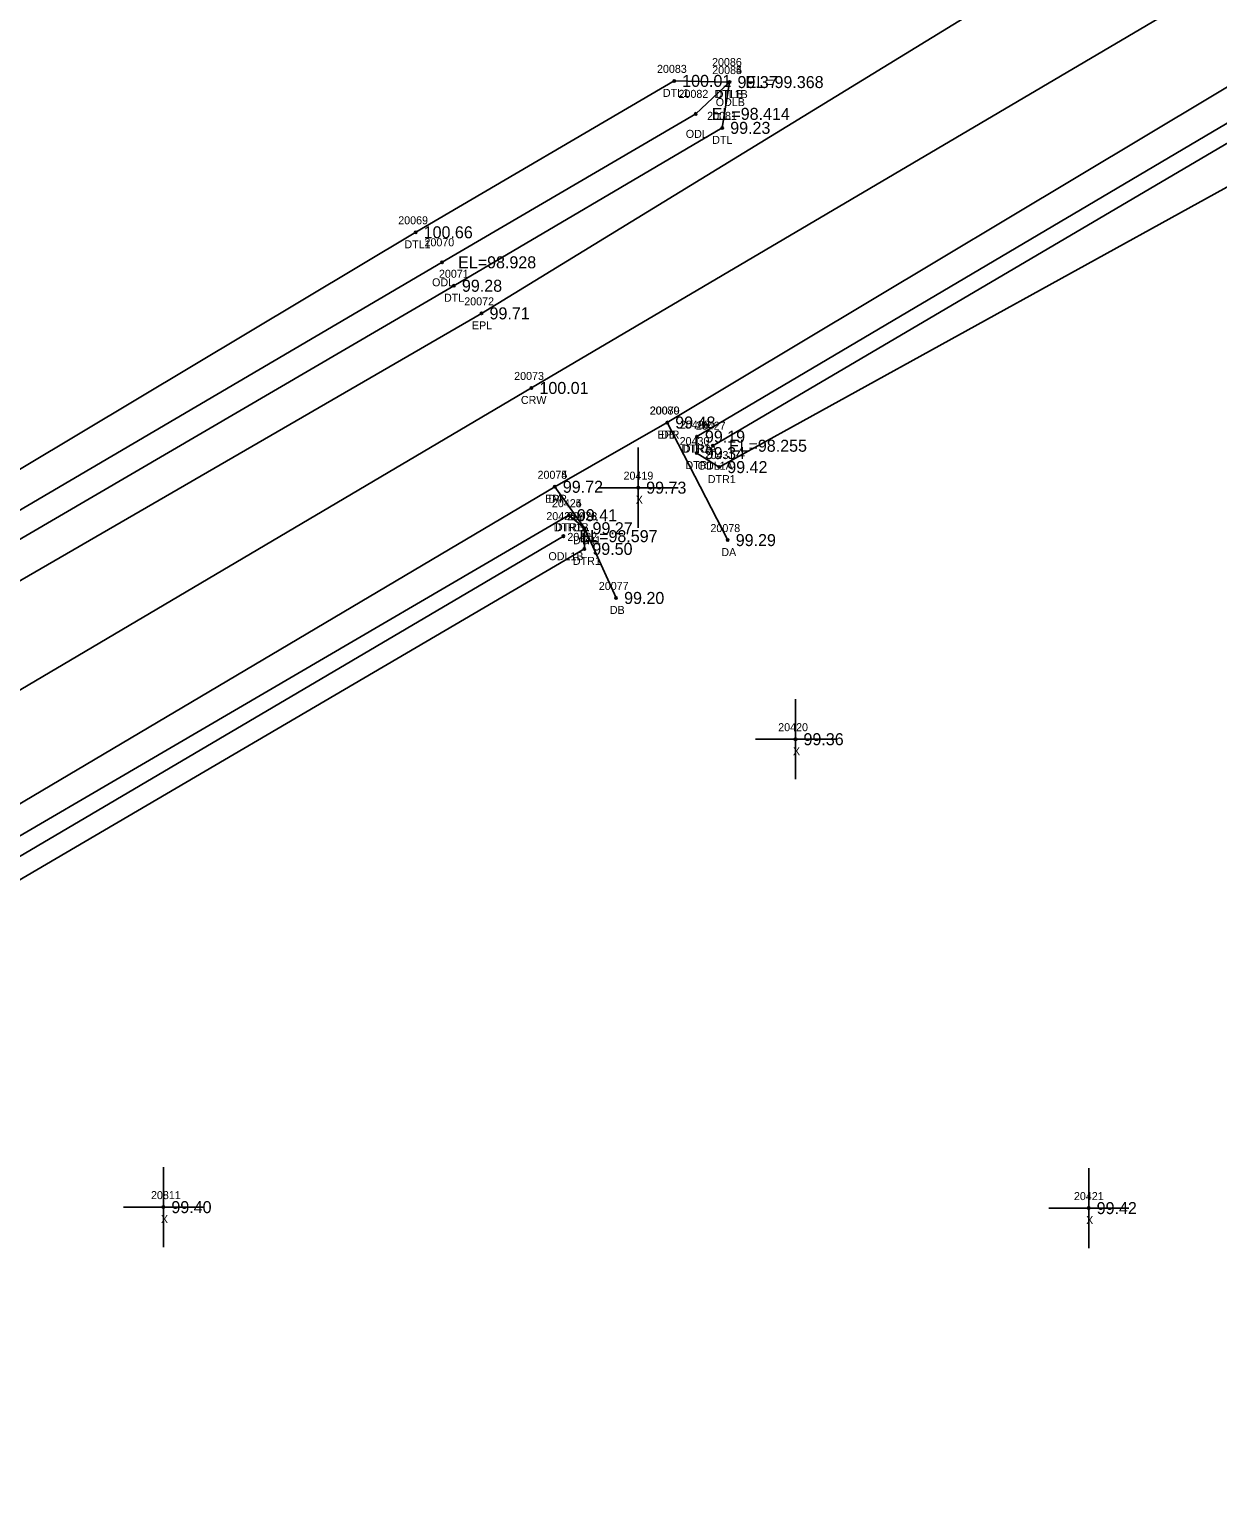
# Model space of a CAD drawing. Extents: x 2530197 to 2532051, y 935230 to 936631.
# Drawn here: x 2530638.9 to 2530787.5, y 935572.8 to 935755.5 of the extents above; entities that cross this region are included whole.
import ezdxf

# ---------------------------------------------------------------- set-up
doc = ezdxf.new("R2010")
doc.units = 0
for name, color, linetype in [('RD_DTM_BkLn1', 7, 'Continuous'), ('RD_EX_Driveway', 7, 'Continuous'), ('RD_EX_Driveway_txCode', 7, 'Continuous'), ('RD_EX_H2O', 7, 'Continuous'), ('RD_EX_H2O_txCode', 7, 'Continuous'), ('RD_EX_Misc', 7, 'Continuous'), ('RD_EX_Misc_txCode', 7, 'Continuous'), ('RD_EX_Road', 7, 'Continuous'), ('RD_EX_Road_txCode', 7, 'Continuous'), ('RD_EX_TX_Driveway_ELEV', 7, 'Continuous'), ('RD_EX_TX_H2O_ELEV', 7, 'Continuous'), ('RD_EX_TX_Misc_ELEV', 7, 'Continuous'), ('RD_EX_TX_Road_ELEV', 7, 'Continuous'), ('RD_HC_Survey_ELEV', 7, 'Continuous'), ('RD_HC_Survey_txCode', 7, 'Continuous'), ('RD_SMD_Locator', 7, 'Continuous')]:
    doc.layers.add(name, color=color, linetype=linetype)

msp = doc.modelspace()

# ---------------------------------------------------------------- linework, layer by layer
at = {"layer": 'RD_DTM_BkLn1'}
msp.add_lwpolyline([(2530212.5, 935590.24), (2530312.97, 935590.25), (2530414.21, 935590.57), (2530470.01, 935593.88), (2530526.51, 935611.77), (2530574.01, 935635.84), (2530615.35, 935659.73), (2530701.7, 935710.7), (2530789.3, 935762.35), (2530874.46, 935813.14), (2530961.78, 935865.4), (2531046.63, 935916.04), (2531084.76, 935938.51)], dxfattribs=at)
at = {"layer": 'RD_EX_Driveway'}
msp.add_line((2530726.23, 935691.69), (2530718.67, 935706.38), dxfattribs=at)
msp.add_lwpolyline([(2530704.62, 935698.35), (2530708.33, 935693.17), (2530712.28, 935684.46)], dxfattribs=at)
at = {"layer": 'RD_EX_H2O'}
for points in [[(2530722.38, 935704.62), (2530796.68, 935748.53), (2530872.47, 935794.26), (2530874.44, 935791.96), (2530875.06, 935785.48)], [(2530724.37, 935703.48), (2530797.51, 935746.5), (2530871.29, 935790.63)], [(2530722.38, 935704.62), (2530722.37, 935702.56), (2530725.17, 935700.81), (2530799.94, 935742.04), (2530875.06, 935785.48)], [(2530543.2, 935642.77), (2530561.27, 935656.09), (2530603.32, 935679.95), (2530687.23, 935730.15), (2530719.54, 935749.07), (2530726.45, 935748.92)], [(2530543.2, 935642.77), (2530564.55, 935651.29), (2530607.02, 935673.87), (2530692.01, 935723.47), (2530725.54, 935743.2), (2530726.45, 935748.92)], [(2530543.2, 935642.77), (2530563.37, 935652.64), (2530605.31, 935676.39), (2530690.53, 935726.4), (2530722.23, 935744.95), (2530726.45, 935748.92)], [(2530585.61, 935271.89), (2530554.63, 935366.84), (2530523, 935462.44), (2530497.71, 935534.53), (2530497.63, 935550.35), (2530501.9, 935567.07), (2530512.76, 935580.06), (2530532.29, 935593.54), (2530580.75, 935621.41), (2530622.78, 935645.99), (2530706.38, 935694.8)], [(2530592.81, 935273.73), (2530561.2, 935369.39), (2530529.39, 935464.13), (2530504.24, 935535.46), (2530502.94, 935549.83), (2530506.75, 935563.82), (2530516.63, 935575.2), (2530535.16, 935588.8), (2530583.24, 935617.5), (2530624.86, 935641.7), (2530708.31, 935690.59), (2530708.33, 935693.17), (2530706.38, 935694.8)], [(2530587.86, 935272.38), (2530557.35, 935368.29), (2530525.38, 935463.03), (2530500.38, 935535.14), (2530499.61, 935550.4), (2530504.44, 935565.67), (2530514.36, 935577.87), (2530533.45, 935591.79), (2530582.01, 935619.78), (2530623.26, 935643.67), (2530705.7, 935692.18)]]:
    msp.add_lwpolyline(points, dxfattribs=at)
at = {"layer": 'RD_EX_Misc'}
for p, q in [((2530715.04, 935693.24), (2530715.04, 935703.24)), ((2530710.04, 935698.24), (2530720.04, 935698.24)), ((2530734.7, 935661.81), (2530734.7, 935671.81)), ((2530729.7, 935666.81), (2530739.7, 935666.81)), ((2530655.7, 935603.34), (2530655.7, 935613.34)), ((2530771.34, 935603.22), (2530771.34, 935613.22)), ((2530650.7, 935608.34), (2530660.7, 935608.34)), ((2530766.34, 935608.22), (2530776.34, 935608.22))]:
    msp.add_line(p, q, dxfattribs=at)
at = {"layer": 'RD_EX_Road'}
for points in [[(2530213.13, 935600.16), (2530313.8, 935600.81), (2530414.15, 935601.13), (2530426.72, 935601.43), (2530429.46, 935603.55), (2530467.67, 935608.62), (2530486.46, 935612.38), (2530518.02, 935622.55), (2530522.16, 935623.68), (2530567.91, 935646.01), (2530609.3, 935670.15), (2530695.46, 935720.02), (2530775.85, 935769.27), (2530868.29, 935824.03), (2530924.84, 935856.95), (2530956.21, 935875.82), (2531040.72, 935926.38), (2531079.45, 935947.76)], [(2530212.44, 935579.72), (2530312.61, 935580.14), (2530402.98, 935580.64), (2530451.06, 935579.53), (2530466.91, 935580.35), (2530487.45, 935583.29), (2530533.43, 935598.45), (2530580.28, 935625.08), (2530621.69, 935649.23), (2530704.62, 935698.35), (2530718.67, 935706.38), (2530795.45, 935752.36), (2530871.33, 935796.67), (2530882.4, 935803.04), (2530947.17, 935842.26), (2530966, 935852.42), (2530992.72, 935868), (2531009.49, 935879.01), (2531052.39, 935904.85), (2531090.88, 935928.23)]]:
    msp.add_lwpolyline(points, dxfattribs=at)
at = {"layer": 'RD_SMD_Locator'}
for centre in [(2530719.54, 935749.07), (2530726.45, 935748.92), (2530726.45, 935748.92), (2530726.45, 935748.92), (2530722.23, 935744.95), (2530725.54, 935743.2), (2530687.23, 935730.15), (2530690.53, 935726.4), (2530692.01, 935723.47), (2530695.46, 935720.02), (2530701.7, 935710.7), (2530718.67, 935706.38), (2530718.67, 935706.38), (2530722.38, 935704.62), (2530722.38, 935704.62), (2530722.37, 935702.56), (2530724.37, 935703.48), (2530725.17, 935700.81), (2530704.62, 935698.35), (2530704.62, 935698.35), (2530715.04, 935698.24), (2530706.38, 935694.8), (2530706.38, 935694.8), (2530708.33, 935693.17), (2530708.33, 935693.17), (2530705.7, 935692.18), (2530726.23, 935691.69), (2530708.31, 935690.59), (2530712.28, 935684.46), (2530734.7, 935666.81), (2530655.7, 935608.34), (2530771.34, 935608.22)]:
    msp.add_circle(centre, 0.15, dxfattribs=at)

# ---------------------------------------------------------------- texts
at = {"layer": 'RD_EX_Driveway_txCode'}
for s, p in [('20079', (2530716.51, 935707.38)), ('DB', (2530717.89, 935704.38)), ('20075', (2530702.46, 935699.35)), ('DA', (2530703.82, 935696.35)), ('20076', (2530706.14, 935694.17)), ('20078', (2530724.07, 935692.69)), ('D', (2530708.02, 935691.17)), ('DA', (2530725.43, 935689.69)), ('20077', (2530710.12, 935685.46)), ('DB', (2530711.5, 935682.46))]:
    msp.add_text(s, height=1, dxfattribs=at).set_placement(p)
at = {"layer": 'RD_EX_H2O_txCode'}
for s, p in [('20086', (2530724.27, 935750.92)), ('20083', (2530717.39, 935750.07)), ('20084', (2530724.29, 935749.92)), ('20085', (2530724.29, 935749.92)), ('DTL1', (2530718.13, 935747.07)), ('20082', (2530720.08, 935746.95)), ('DTL1B', (2530724.57, 935746.92)), ('ODLB', (2530724.73, 935745.92)), ('DTLB', (2530724.73, 935746.92)), ('20081', (2530723.66, 935744.2)), ('ODL', (2530720.99, 935741.95)), ('DTL', (2530724.29, 935741.2)), ('20069', (2530685.05, 935731.15)), ('DTL1', (2530685.82, 935728.15)), ('20070', (2530688.33, 935728.4)), ('ODL', (2530689.28, 935723.4)), ('20071', (2530690.14, 935724.47)), ('DTL', (2530690.77, 935721.47)), ('20428', (2530720.26, 935705.62)), ('20429', (2530720.26, 935705.62)), ('20427', (2530722.25, 935705.48)), ('20430', (2530720.22, 935703.56)), ('DTR1A', (2530720.46, 935702.62)), ('DTRA', (2530720.62, 935702.62)), ('20431', (2530723.34, 935701.81)), ('DTR1', (2530720.94, 935700.56)), ('ODL1A', (2530722.47, 935700.48)), ('DTR1', (2530723.74, 935698.81)), ('20424', (2530704.26, 935695.8)), ('20425', (2530704.26, 935695.8)), ('20426', (2530703.56, 935694.18)), ('20423', (2530706.21, 935694.17)), ('DTR1B', (2530704.47, 935692.8)), ('DTRB', (2530704.64, 935692.8)), ('20422', (2530706.19, 935691.59)), ('DTR1', (2530706.89, 935691.17)), ('ODL1B', (2530703.82, 935689.18)), ('DTR1', (2530706.88, 935688.59))]:
    msp.add_text(s, height=1, dxfattribs=at).set_placement(p)
at = {"layer": 'RD_EX_Misc_txCode'}
for s, p in [('20419', (2530713.21, 935699.24)), ('X', (2530714.73, 935696.24)), ('20420', (2530732.54, 935667.81)), ('X', (2530734.38, 935664.81)), ('20811', (2530654.15, 935609.34)), ('20421', (2530769.5, 935609.22)), ('X', (2530655.39, 935606.34)), ('X', (2530771.02, 935606.22))]:
    msp.add_text(s, height=1, dxfattribs=at).set_placement(p)
at = {"layer": 'RD_EX_Road_txCode'}
for s, p in [('20072', (2530693.3, 935721.02)), ('EPL', (2530694.26, 935718.02)), ('20080', (2530716.47, 935707.38)), ('EPR', (2530717.44, 935704.38)), ('20074', (2530702.46, 935699.35)), ('EPR', (2530703.39, 935696.35))]:
    msp.add_text(s, height=1, dxfattribs=at).set_placement(p)
at = {"layer": 'RD_EX_TX_Driveway_ELEV'}
for s, p in [('99.48', (2530719.67, 935705.63)), ('99.72', (2530705.62, 935697.6)), ('99.27', (2530709.33, 935692.42)), ('99.29', (2530727.23, 935690.94)), ('99.20', (2530713.28, 935683.71))]:
    msp.add_text(s, height=1.5, dxfattribs=at).set_placement(p)
at = {"layer": 'RD_EX_TX_H2O_ELEV'}
for s, p in [('100.01', (2530720.54, 935748.32)), ('99.37', (2530727.45, 935748.17)), ('99.37', (2530727.45, 935748.17)), ('EL=99.368', (2530728.45, 935748.17)), ('EL=98.414', (2530724.23, 935744.2)), ('99.23', (2530726.54, 935742.45)), ('100.66', (2530688.23, 935729.4)), ('EL=98.928', (2530692.53, 935725.65)), ('99.28', (2530693.01, 935722.72)), ('99.19', (2530723.38, 935703.87)), ('99.19', (2530723.38, 935703.87)), ('EL=98.255', (2530726.37, 935702.73)), ('99.34', (2530723.37, 935701.81)), ('99.42', (2530726.17, 935700.06)), ('99.41', (2530707.38, 935694.05)), ('99.41', (2530707.38, 935694.05)), ('99.27', (2530709.33, 935692.42)), ('EL=98.597', (2530707.7, 935691.43)), ('99.50', (2530709.31, 935689.84))]:
    msp.add_text(s, height=1.5, dxfattribs=at).set_placement(p)
at = {"layer": 'RD_EX_TX_Misc_ELEV'}
for s, p in [('99.73', (2530716.04, 935697.49)), ('99.36', (2530735.7, 935666.06)), ('99.40', (2530656.7, 935607.59)), ('99.42', (2530772.34, 935607.47))]:
    msp.add_text(s, height=1.5, dxfattribs=at).set_placement(p)
at = {"layer": 'RD_EX_TX_Road_ELEV'}
for s, p in [('99.71', (2530696.46, 935719.27)), ('99.48', (2530719.67, 935705.63)), ('99.72', (2530705.62, 935697.6))]:
    msp.add_text(s, height=1.5, dxfattribs=at).set_placement(p)
at = {"layer": 'RD_HC_Survey_ELEV'}
msp.add_text('100.01', height=1.5, dxfattribs=at).set_placement((2530702.7, 935709.95))
at = {"layer": 'RD_HC_Survey_txCode'}
for s, p in [('20073', (2530699.54, 935711.7)), ('CRW', (2530700.38, 935708.7))]:
    msp.add_text(s, height=1, dxfattribs=at).set_placement(p)

doc.saveas('drawing.dxf')
